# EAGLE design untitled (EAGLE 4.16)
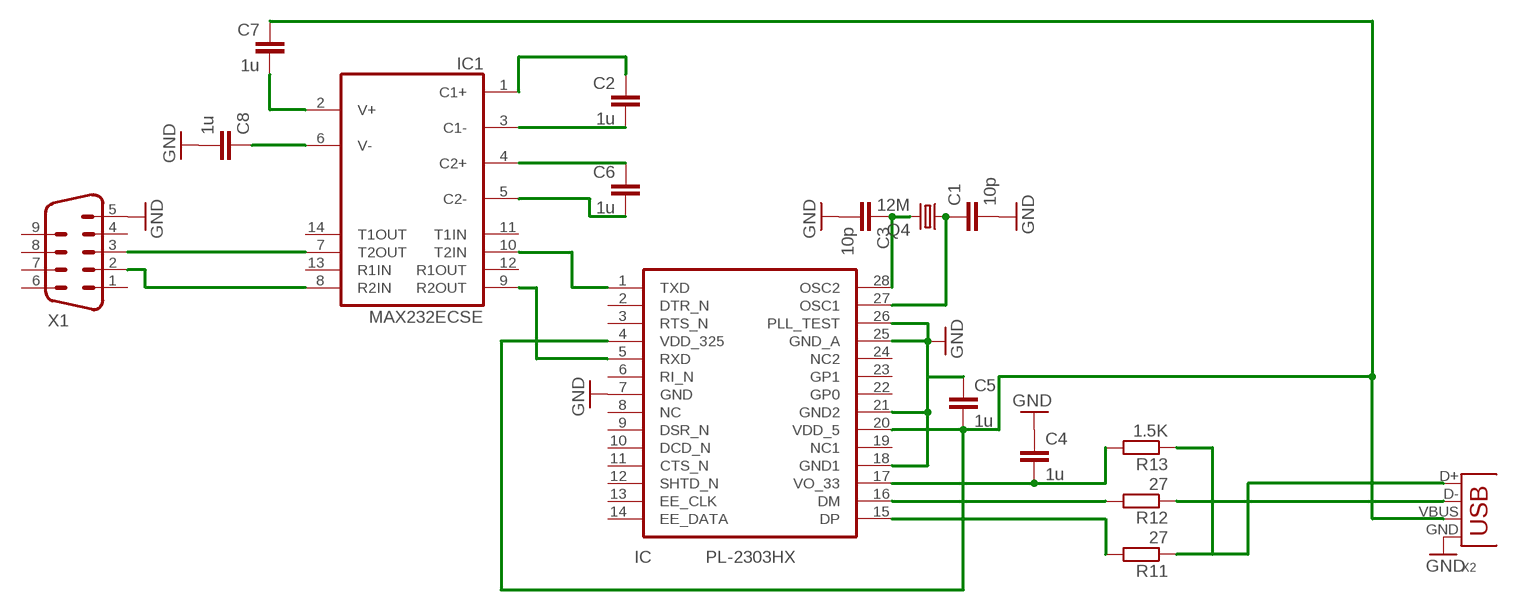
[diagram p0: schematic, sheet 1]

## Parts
C1  10p  C-EUC1206  [C1206]
C2  1u  C-EUC1206  [C1206]
C3  10p  C-EUC1206  [C1206]
C4  1u  C-EUC1206  [C1206]
C5  1u  C-EUC1206  [C1206]
C6  1u  C-EUC1206  [C1206]
C7  1u  C-EUC1206  [C1206]
C8  1u  C-EUC1206  [C1206]
IC1  MAX232ECSE  [SO16]
Q4  12M  CRYTALHC49S  [HC49/S]
R11  27  R-EU_R1206  [R1206]
R12  27  R-EU_R1206  [R1206]
R13  1.5K  R-EU_R1206  [R1206]
U$1  PL-2303HX  [SSOP-28]
X1  M09D  [M09D]
X2  USB-MB-S  [USB-MB-S]

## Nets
GND: C1.2 C3.2 C4.1 C5.1 C8.2 U$1.7(GND) U$1.18(GND1) U$1.21(GND2) U$1.25(GND_A) U$1.26(PLL_TEST) X1.5 X2.GND
N$1: C2.1 IC1.1(C1+)
N$2: C2.2 IC1.3(C1-)
N$3: C6.1 IC1.4(C2+)
N$4: C6.2 IC1.5(C2-)
N$5: IC1.10(T2IN) U$1.1(TXD)
N$6: C8.1 IC1.6(V-)
N$7: IC1.9(R2OUT) U$1.5(RXD)
N$8: C7.2 IC1.2(V+)
N$9: IC1.8(R2IN) X1.2
N$10: IC1.7(T2OUT) X1.3
N$12: R11.2 U$1.15(DP)
N$21: R11.1 R13.1 X2.D+
N$22: C3.1 Q4.2 U$1.28(OSC2)
N$23: C1.1 Q4.1 U$1.27(OSC1)
N$25: R12.2 U$1.16(DM)
N$26: C4.2 R13.2 U$1.17(VO_33)
N$27: R12.1 X2.D-
VCC: C5.2 C7.1 U$1.4(VDD_325) U$1.20(VDD_5) X2.VBUS
Unconnected: IC1.11(T1IN) IC1.12(R1OUT) IC1.13(R1IN) IC1.14(T1OUT) U$1.2(DTR_N) U$1.3(RTS_N) U$1.6(RI_N) U$1.8(NC) U$1.9(DSR_N) U$1.10(DCD_N) U$1.11(CTS_N) U$1.12(SHTD_N) U$1.13(EE_CLK) U$1.14(EE_DATA) U$1.19(NC1) U$1.22(GP0) U$1.23(GP1) U$1.24(NC2) X1.1 X1.4 X1.6 X1.7 X1.8 X1.9

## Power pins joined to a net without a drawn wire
GND: IC1.15(GND)
VCC: IC1.16(VCC)

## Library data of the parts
C1-C8 = RCL:C-EU: CAPACITOR, European symbol
IC1 = maxim-8:MAX232*: RS232 TRANSEIVER
Q4 = CRYSTAL:CRYTAL: CRYSTAL
R11-R13 = RCL:R-EU_: RESISTOR, European symbol
U$1 = Prolific:PL-2303HX
X1 = CON-SUBD:M09: SUB-D
X2 = con-usb-3:USB: USB Connectors

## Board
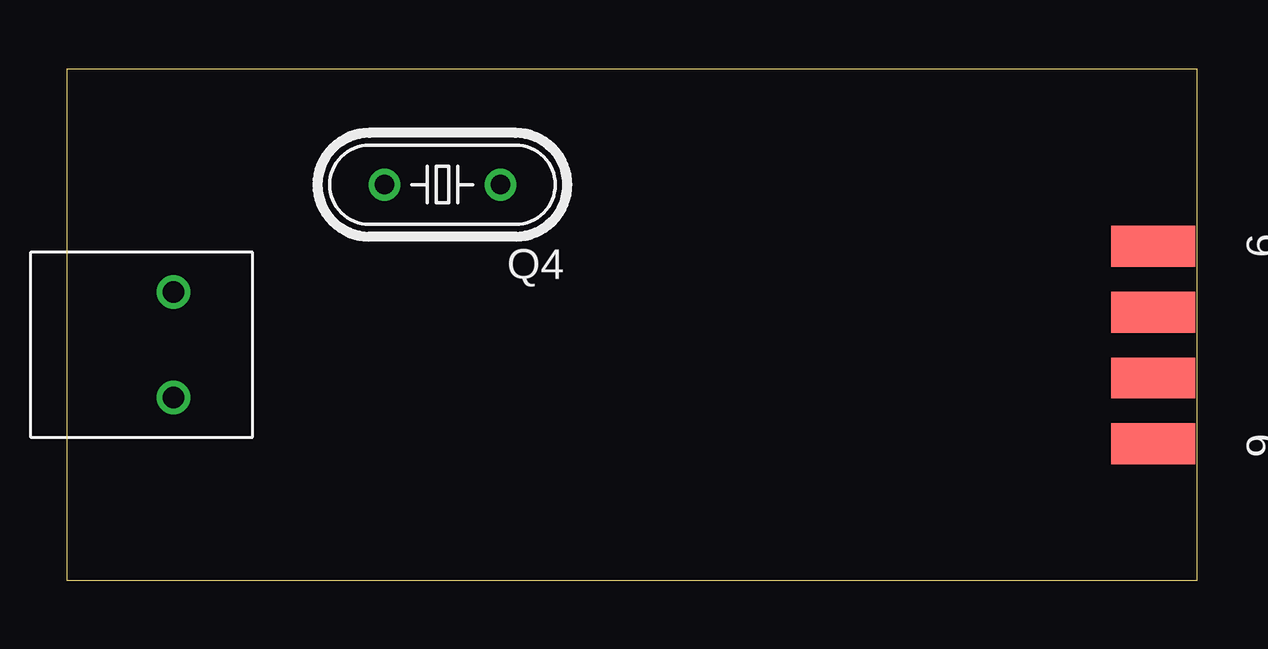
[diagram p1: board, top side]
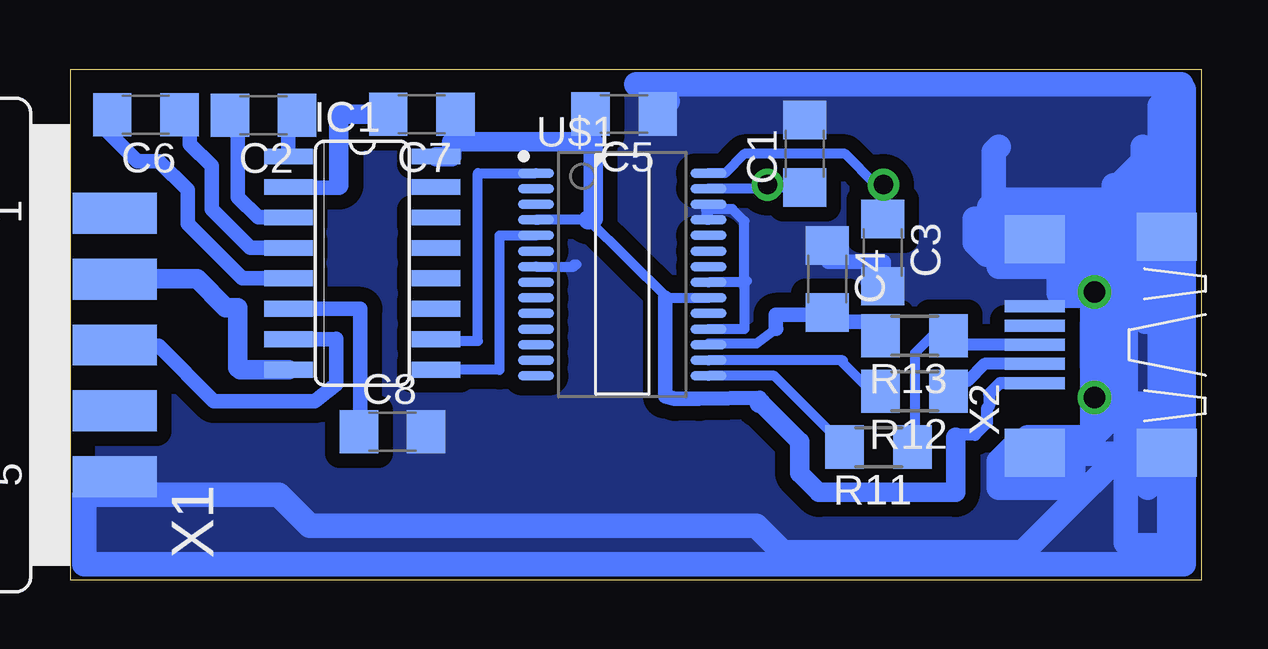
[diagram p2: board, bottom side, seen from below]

Size 47.1 x 21.3 mm. Coordinates in mm from the lower left corner, seen from the top.
Outline: 0,0 47.1,0 47.1,21.3 0,21.3 0,0
Copper layers (1*16): Top 0.035mm / dielectric 1.5mm / Bottom 0.035mm
Design rules "default": minimum track width 10mil, minimum drill 24mil, track to track 8mil, track to pad 8mil, pad to pad 8mil, via to via 8mil, smd to smd 8mil, copper to edge 40mil, drill to drill 8mil, minimum pad ring 10mil, minimum via ring 8mil, stop-mask expansion 4mil, vias tented up to drill 0mil, thermal gap 10mil

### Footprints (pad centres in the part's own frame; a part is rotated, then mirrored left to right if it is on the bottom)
C1206 = smd 1.6 x 1.8: 1 -1.4,0; 2 1.4,0
SO16 = smd 0.66 x 2.032: 1 -4.445,-3.073; 2 -3.175,-3.073; 3 -1.905,-3.073; 4 -0.635,-3.073; 5 0.635,-3.073; 6 1.905,-3.073; 7 3.175,-3.073; 8 4.445,-3.073; 9 4.445,3.073; 10 3.175,3.073; 11 1.905,3.073; 12 0.635,3.073; 13 -0.635,3.073; 14 -1.905,3.073; 15 -3.175,3.073; 16 -4.445,3.073
HC49/S = drill 0.813 round: 1 -2.413,0; 2 2.413,0
R1206 = smd 1.6 x 1.803: 1 -1.422,0; 2 1.422,0
SSOP-28 = smd 1.5 x 0.4: 1 -3.6,4.225; 2 -3.6,3.575; 3 -3.6,2.925; 4 -3.6,2.275; 5 -3.6,1.625; 6 -3.6,0.975; 7 -3.6,0.325; 8 -3.6,-0.325; 9 -3.6,-0.975; 10 -3.6,-1.625; 11 -3.6,-2.275; 12 -3.6,-2.925; 13 -3.6,-3.575; 14 -3.6,-4.225; 15 3.6,-4.225; 16 3.6,-3.575; 17 3.6,-2.925; 18 3.6,-2.275; 19 3.6,-1.625; 20 3.6,-0.975; 21 3.6,-0.325; 22 3.6,0.325; 23 3.6,0.975; 24 3.6,1.625; 25 3.6,2.275; 26 3.6,2.925; 27 3.6,3.575; 28 3.6,4.225
M09D = smd 1.7 x 3.5: 1 5.486,-6.045; 2 2.743,-6.045; 3 0,-6.045; 4 -2.743,-6.045; 5 -5.486,-6.045 | smd 1.7 x 3.5 bottom: 6 4.115,-6.045; 7 1.372,-6.045; 8 -1.372,-6.045; 9 -4.115,-6.045
USB-MB-S = smd 2.5 x 0.5: D+ 2.5,0; D- 2.5,0.8; GND 2.5,-1.6; ID 2.5,-0.8; VBUS 2.5,1.6 | smd 2.5 x 2: P$1 -3,-4.5; P$2 -3,4.5; P$3 2.5,-4.4; P$4 2.5,4.5 | drill 0.9 round: P$5 0,2.2; P$6 0,-2.2

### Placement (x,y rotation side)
C1  16.52,17.78 90 bottom
C2  39.07,19.38 180 bottom
C3  13.26,13.66 270 bottom
C4  15.58,12.56 270 bottom
C5  24.04,19.44 180 bottom
C6  43.97,19.4 180 bottom
C7  32.47,19.42 180 bottom
C8  33.69,6.2 0 bottom
IC1  34.95,13.22 270 bottom
Q4  15.65,16.49 180 top
R11  13.44,5.56 180 bottom
R12  11.94,7.88 180 bottom
R13  11.94,10.2 180 bottom
U$1  24.12,12.75 0 bottom
X1  51.31,9.81 90 bottom
X2  4.44,9.82 180 bottom

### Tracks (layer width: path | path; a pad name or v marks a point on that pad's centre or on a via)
GND
  Bottom 0.406: U$1.7 26.13,13.08 26.13,13.17 26.03,13.17 | 19.03,12.43 18.98,12.43 18.93,12.47 | 19.13,12.43 19.03,12.43 | 19.13,12.43 U$1.21 | 20.63,15.47 20.59,15.03 | 20.59,15.03 U$1.25 U$1.26 20.44,15.68 | U$1.18 19.04,10.48 19.03,10.47 19.03,12.43 | 19.03,12.43 19.03,12.47 | 20.59,15.03 20.59,15.43 20.63,15.47 | 20.63,15.47 19.53,15.47 19.03,14.97 19.03,12.57 19.13,12.47 19.13,12.43
  Bottom 0.61: C3.2 13.23,12.26 13.23,13.27 15.53,13.27 15.53,13.96 C4.1
  Bottom 1.016: 3.43,16.47 1.63,16.47 | 3.43,16.47 3.63,16.47 | 3.43,16.47 2.23,17.67 2.23,17.27 2.13,17.17 2.13,17.77 2.43,18.07 2.43,15.67 1.13,14.37 2.53,14.37 3.53,15.37 3.43,15.37 2.63,14.57 2.63,11.07 2.33,10.77 1.43,10.77 1.43,12.97 2.03,13.57 2.03,12.17 1.93,12.07 | 1.93,12.07 1.93,11.17 | 1.93,12.07 1.93,14.67 2.33,15.07 9.43,15.07 9.43,14.07 8.93,13.57 8.73,13.57 8.63,13.67 8.63,17.87 8.43,18.07 | 1.33,16.47 1.33,1.47 3.03,1.47 3.13,1.57 3.13,4.77 | 3.13,4.77 3.13,16.07 | 3.13,4.77 2.23,3.87 2.23,7.37 3.63,7.37 4.03,6.97 | 4.03,6.97 4.53,6.47 4.53,13.67 4.33,13.87 5.93,13.87 | 5.93,13.87 6.93,13.87 | 5.93,13.87 5.43,14.37 5.43,15.87 8.53,15.87 8.83,15.57 6.23,15.57 3.83,13.17 3.83,7.17 4.03,6.97 | 4.03,6.97 4.03,15.77 4.13,15.87 5.63,15.87 8.43,13.07 5.13,13.07 5.13,11.87 5.83,11.87 5.93,11.97 5.93,14.47 5.23,15.17 5.03,15.17 3.53,13.67 3.53,6.97 4.53,5.97 7.23,5.97 7.63,5.57 7.83,5.57 8.43,4.97 8.43,3.87 5.83,3.87 5.33,4.37 5.33,5.17 5.43,5.27 2.23,5.27 1.03,6.47 | 0.73,20.47 0.73,0.67 46.53,0.67 46.53,3.57 38.43,3.57 37.13,2.27 18.53,2.27 17.43,1.17 7.43,1.17 1.73,6.87 1.73,19.77 0.83,20.67 22.93,20.67 | 22.93,20.67 23.53,20.67 | 22.93,20.67 22.23,19.97
  pour Bottom (isolate 0.61, no thermals): 0.33,21.27 47.03,21.27 46.93,0.67 0.33,0.57
N$1
  Bottom 0.61: C2.1 38.03,19.28 IC1.1
N$2
  Bottom 0.61: IC1.3 39.29,15.12 40.13,15.97 40.13,18.57 40.84,19.28 C2.2
N$3
  Bottom 0.61: IC1.4 39.62,13.86 41.23,15.47 41.23,17.27 42.13,18.17 42.13,18.87 42.63,19.37 42.6,19.4 C6.1
N$4
  Bottom 0.61: IC1.5 39.95,12.59 42.23,14.87 42.23,16.27 43.43,17.47 44.33,17.47 45.53,18.67 45.53,19.07 45.37,19.23 C6.2
N$5
  Bottom 0.406: U$1.1 30.13,16.97 30.13,9.97 31.03,9.97 31.03,10.04 | 31.03,10.04 31.03,10.07 | 31.03,10.04 IC1.10
N$6
  Bottom 0.61: C8.1 35.03,6.9 35.03,11.32 IC1.6
N$7
  Bottom 0.406: U$1.5 29.23,14.38 29.23,8.77 31.13,8.77 31.13,8.78 IC1.9
N$8
  Bottom 0.61: 35.93,16.47 35.93,16.37 37.93,16.37 37.93,16.39 IC1.2
  Bottom 0.813: C7.2 35.93,19.42 35.93,16.47
N$9
  Bottom 0.813: IC1.8 40.04,8.78 40.13,8.87 40.13,11.37 40.63,11.37 41.83,12.57 45.03,12.57 45.05,12.55 X1.2
N$10
  Bottom 0.61: IC1.7 36.05,10.04 36.03,10.07 36.03,8.17 36.93,7.47 41.13,7.47 43.43,9.77 45.23,9.77 45.23,9.78 X1.3
N$12
  Bottom 0.406: R11.2 14.84,5.56 14.83,5.57 17.79,8.53 U$1.15
N$21
  Bottom 0.406: R11.1 12.02,6.28 11.93,6.37 11.93,9.47 11.03,10.37 10.83,10.37 10.83,10.27 10.73,10.27
  Bottom 0.5: 10.73,10.27 10.66,10.2 R13.1 10.13,9.82 X2.D+
N$22
  Bottom 0.406: Q4.2 13.55,16.49 14.83,17.77 19.03,17.77 19.83,16.97 20.43,16.97 20.44,16.97 U$1.28
  Bottom 0.61: 13.24,16.56 13.23,16.57 | 13.24,16.56 Q4.2 | C3.1 13.26,16.54 13.24,16.56
N$23
  Bottom 0.406: 18.03,16.37 18.06,16.4 Q4.1 | U$1.27 18.08,16.32 18.03,16.37 | C1.1 16.82,16.36 16.83,16.37 18.03,16.37
N$25
  Bottom 0.406: R12.2 13.54,7.68 14.93,9.07 14.93,9.17 U$1.16
N$26
  Bottom 0.406: 17.71,10.49 18.53,9.87 20.53,9.87 20.52,9.86 U$1.17
  Bottom 0.61: R13.2 13.83,10.2 13.83,10.77 15.43,10.77 15.43,11.16 C4.2 15.73,11.16 15.73,11.07 17.73,11.07 17.73,10.49 17.71,10.49
N$27
  Bottom 0.5: 10.12,7.88 R12.1 10.52,7.91 10.53,7.92 10.13,8.32 9.73,8.32 9.03,9.02 X2.D-
VCC
  Bottom 0.406: U$1.20 22.33,11.78 22.23,11.78 25.53,15.02 27.63,15.02 27.68,15.03 U$1.4
  Bottom 0.5: 10.23,5.97 arc90 10.13,6.07 9.43,6.07 8.93,6.57 8.93,7.17 8.83,7.27 8.83,7.77 8.38,8.22 X2.VBUS
  Bottom 0.61: 18.46,7.56 18.4,7.38 18.38,7.62 20.93,7.57 21.93,7.57 22.33,7.67 22.33,11.78 | C5.2 25.4,18.94 25.33,18.87 25.33,18.27
  Bottom 0.813: 18.4,7.38 18.34,7.38 16.73,5.77 16.73,4.47 15.93,3.67 10.23,3.67 10.23,5.97 | IC1.16 31.23,17.66 31.23,18.27 31.03,18.27 | 25.53,15.02 25.33,15.07 25.33,18.27 31.03,18.27 | C7.1 31.03,19.42 31.03,18.27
